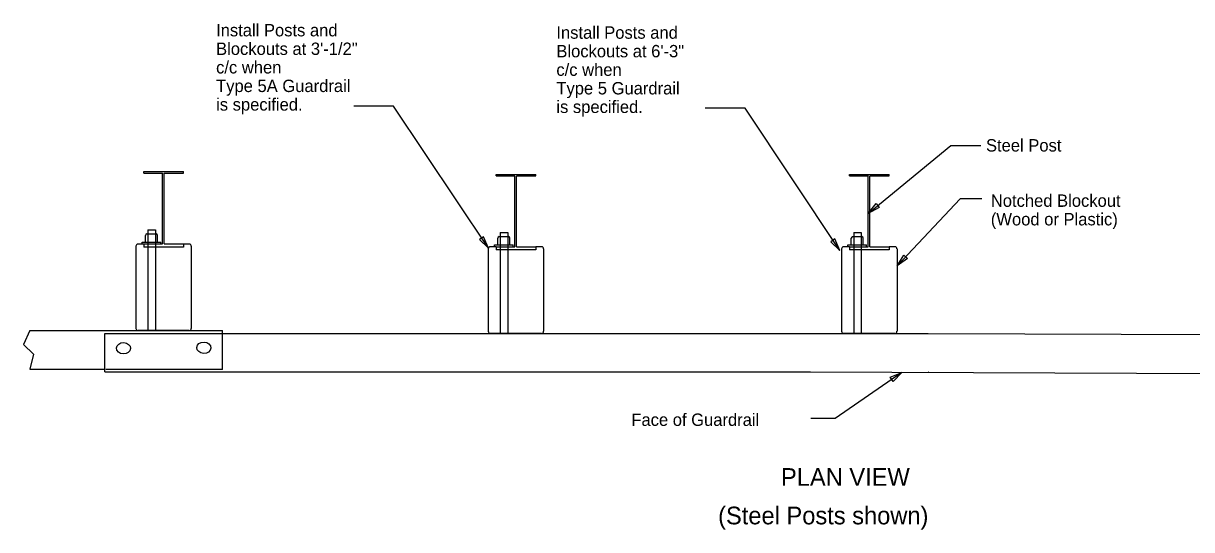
# Model space of a CAD drawing. Extents: x -0.7 to 89.2, y -3.6 to 22.
# Drawn here: x 61.98 to 75.19, y 7.54 to 13.27 of the extents above; entities that cross this region are included whole.
import ezdxf

# ---------------------------------------------------------------- set-up
doc = ezdxf.new("R2010")
doc.units = 0
doc.layers.add('Default', color=7, linetype='Continuous')

msp = doc.modelspace()

# ---------------------------------------------------------------- linework, layer by layer
at = {"layer": 'Default'}
for p, q in [((66.164, 12.335), (65.714, 12.335)), ((67.237, 10.725), (66.164, 12.335)), ((70.138, 12.31), (69.688, 12.31)), ((71.211, 10.7), (70.138, 12.31)), ((63.339, 11.592), (63.583, 11.592)), ((63.339, 11.576), (63.339, 11.592)), ((63.339, 11.576), (63.552, 11.576)), ((63.551, 10.774), (63.551, 11.574)), ((63.57, 11.575), (63.787, 11.575)), ((63.571, 10.774), (63.571, 11.574)), ((63.583, 11.592), (63.787, 11.592)), ((63.787, 11.575), (63.787, 11.592)), ((67.324, 11.561), (67.567, 11.561)), ((67.324, 11.544), (67.324, 11.561)), ((67.324, 11.544), (67.537, 11.544)), ((67.536, 10.743), (67.536, 11.542)), ((67.555, 11.544), (67.771, 11.544)), ((67.555, 10.743), (67.555, 11.542)), ((67.567, 11.561), (67.771, 11.561)), ((67.771, 11.544), (67.771, 11.561)), ((71.32, 11.561), (71.563, 11.561)), ((71.32, 11.544), (71.32, 11.561)), ((71.32, 11.544), (71.533, 11.544)), ((71.532, 10.743), (71.532, 11.542)), ((71.551, 11.544), (71.767, 11.544)), ((71.551, 10.743), (71.551, 11.542)), ((71.563, 11.561), (71.767, 11.561)), ((71.767, 11.544), (71.767, 11.561)), ((71.857, 10.528), (72.571, 11.285)), ((72.816, 11.284), (72.571, 11.285)), ((63.36, 10.796), (63.36, 10.87)), ((63.374, 10.89), (63.48, 10.89)), ((63.386, 10.934), (63.386, 9.793)), ((63.386, 10.934), (63.471, 10.934)), ((63.471, 10.934), (63.471, 9.793)), ((63.493, 10.796), (63.493, 10.87)), ((67.344, 10.765), (67.344, 10.839)), ((67.358, 10.859), (67.464, 10.859)), ((67.371, 10.903), (67.371, 9.762)), ((67.371, 10.903), (67.456, 10.903)), ((67.456, 10.903), (67.456, 9.762)), ((67.477, 10.765), (67.477, 10.839)), ((71.34, 10.765), (71.34, 10.839)), ((71.354, 10.859), (71.46, 10.859)), ((71.367, 10.903), (71.367, 9.762)), ((71.367, 10.903), (71.452, 10.903)), ((71.452, 10.903), (71.452, 9.762)), ((71.473, 10.765), (71.473, 10.839)), ((63.25, 10.748), (63.25, 9.818)), ((63.339, 10.773), (63.272, 10.773)), ((63.32, 10.774), (63.32, 10.796)), ((63.321, 10.796), (63.533, 10.796)), ((63.339, 10.774), (63.551, 10.774)), ((63.339, 10.773), (63.339, 10.738)), ((63.787, 10.738), (63.339, 10.738)), ((63.533, 10.774), (63.533, 10.795)), ((63.571, 10.774), (63.787, 10.774)), ((63.787, 10.773), (63.787, 10.738)), ((63.854, 10.773), (63.787, 10.773)), ((63.876, 10.748), (63.876, 9.818)), ((67.234, 10.717), (67.234, 9.787)), ((67.324, 10.742), (67.257, 10.742)), ((67.305, 10.765), (67.517, 10.765)), ((67.305, 10.743), (67.305, 10.765)), ((67.324, 10.743), (67.536, 10.743)), ((67.324, 10.742), (67.324, 10.707)), ((67.771, 10.707), (67.324, 10.707)), ((67.517, 10.743), (67.517, 10.764)), ((67.555, 10.743), (67.771, 10.743)), ((67.771, 10.742), (67.771, 10.707)), ((67.838, 10.742), (67.771, 10.742)), ((67.861, 10.717), (67.861, 9.787)), ((71.23, 10.717), (71.23, 9.787)), ((71.32, 10.742), (71.253, 10.742)), ((71.301, 10.765), (71.513, 10.765)), ((71.301, 10.743), (71.301, 10.765)), ((71.32, 10.743), (71.532, 10.743)), ((71.32, 10.742), (71.32, 10.707)), ((71.767, 10.707), (71.32, 10.707)), ((71.513, 10.743), (71.513, 10.764)), ((71.551, 10.743), (71.767, 10.743)), ((71.767, 10.742), (71.767, 10.707)), ((71.834, 10.742), (71.767, 10.742)), ((71.857, 10.717), (71.857, 9.787)), ((62.049, 9.793), (61.978, 9.637)), ((62.049, 9.793), (64.231, 9.793)), ((63.854, 9.793), (63.272, 9.793)), ((64.231, 9.763), (64.231, 9.793)), ((62.899, 9.326), (62.899, 9.762)), ((62.899, 9.762), (67.751, 9.762)), ((64.231, 9.355), (64.231, 9.753)), ((67.838, 9.762), (67.257, 9.762)), ((67.744, 9.762), (72.211, 9.762)), ((71.834, 9.762), (71.253, 9.762)), ((72.211, 9.762), (80.141, 9.73)), ((61.978, 9.637), (62.092, 9.527)), ((62.092, 9.527), (62.049, 9.356)), ((62.049, 9.356), (62.899, 9.356)), ((62.899, 9.326), (70.879, 9.325)), ((62.91, 9.356), (64.231, 9.356)), ((64.231, 9.356), (64.231, 9.356)), ((70.879, 9.325), (78.864, 9.294)), ((72.211, 9.325), (72.212, 9.325))]:
    msp.add_line(p, q, dxfattribs=at)
for points in [[(71.531, 11.12), (72.467, 11.887), (72.804, 11.887)], [(71.912, 9.321), (71.159, 8.8), (70.883, 8.8)]]:
    msp.add_lwpolyline(points, dxfattribs=at)
for points in [[(71.657, 11.188), (71.531, 11.12), (71.621, 11.231)], [(67.134, 10.824), (67.237, 10.725), (67.18, 10.856)], [(71.108, 10.799), (71.211, 10.7), (71.154, 10.831)], [(71.974, 10.609), (71.857, 10.528), (71.934, 10.648)], [(71.78, 9.266), (71.912, 9.321), (71.812, 9.219)]]:
    msp.add_lwpolyline(points, close=True, dxfattribs=at)
for centre, major_axis, ratio, start_param, end_param in [((63.377, 10.87), (0, -0.0207), 0.850089, 3.345604, 4.722982), ((63.476, 10.869), (0, -0.0207), 0.850089, 1.586202, 2.897406), ((67.362, 10.838), (0, -0.0207), 0.850089, 3.345604, 4.722982), ((67.46, 10.838), (0, -0.0207), 0.850089, 1.586202, 2.897406), ((71.358, 10.838), (0, -0.0207), 0.850089, 3.345604, 4.722982), ((71.456, 10.838), (0, -0.0207), 0.850089, 1.586202, 2.897406), ((63.272, 10.748), (0, -0.0249), 0.9, 3.141593, 4.712389), ((63.854, 10.748), (0, 0.0249), 0.9, 4.712389, 6.283185), ((67.257, 10.717), (0, -0.0249), 0.9, 3.141593, 4.712389), ((67.838, 10.717), (0, 0.0249), 0.9, 4.712389, 6.283185), ((71.253, 10.717), (0, -0.0249), 0.9, 3.141593, 4.712389), ((71.834, 10.717), (0, 0.0249), 0.9, 4.712389, 6.283185), ((63.272, 9.818), (0, -0.0249), 0.9, 4.712389, 6.283185), ((63.854, 9.818), (0, 0.0249), 0.9, 3.141593, 4.712389), ((67.257, 9.787), (0, -0.0249), 0.9, 4.712389, 6.283185), ((67.838, 9.787), (0, 0.0249), 0.9, 3.141593, 4.712389), ((71.253, 9.787), (0, -0.0249), 0.9, 4.712389, 6.283185), ((71.834, 9.787), (0, 0.0249), 0.9, 3.141593, 4.712389)]:
    msp.add_ellipse(centre, major_axis=major_axis, ratio=ratio, start_param=start_param, end_param=end_param, dxfattribs=at)
for centre in [(63.11, 9.594), (64.018, 9.599)]:
    msp.add_ellipse(centre, major_axis=(0.0792, -0.0028), ratio=0.818413, dxfattribs=at)

# ---------------------------------------------------------------- texts
for s, height, p in [('Install Posts and', 0.14, (64.157, 13.123)), ('Install Posts and', 0.14, (68.005, 13.096)), ('Blockouts at 3\'-1/2"', 0.14, (64.157, 12.913)), ('Blockouts at 6\'-3"', 0.14, (68.005, 12.886)), ('c/c when', 0.14, (64.157, 12.703)), ('c/c when', 0.14, (68.005, 12.676)), ('Type 5A Guardrail', 0.14, (64.157, 12.493)), ('Type 5 Guardrail', 0.14, (68.005, 12.466)), ('is specified.', 0.14, (64.157, 12.283)), ('is specified.', 0.14, (68.005, 12.256)), ('Steel Post', 0.14, (72.863, 11.82)), ('Notched Blockout', 0.14, (72.918, 11.194)), ('(Wood or Plastic)', 0.14, (72.918, 10.984)), ('Face of Guardrail', 0.14, (68.853, 8.715)), ('PLAN VIEW', 0.2, (70.545, 8.037)), ('(Steel Posts shown)', 0.2, (69.834, 7.601))]:
    msp.add_text(s, height=height, dxfattribs=at).set_placement(p)

doc.saveas('drawing.dxf')
